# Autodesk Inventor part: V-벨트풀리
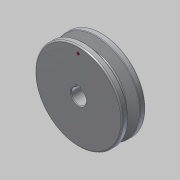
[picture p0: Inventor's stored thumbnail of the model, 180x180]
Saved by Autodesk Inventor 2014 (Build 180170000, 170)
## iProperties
Created: 2016-08
Part Number: V-벨트풀리
Material: 알루미늄 6061
Document SubType Name: Modeling
Designer: mduedu
Density: 2.71 g/cm^3
Appearance: 알루미늄 - 평지
Author: mduedu
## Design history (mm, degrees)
sketch "스케치1"
  geometry: L1 (0, 9.5)-(0, -9.5); L2 (0, 9.5)-(35, 9.5); L3 (35, 9.5)-(35, 4.825); L4 (35, 4.825)-(26, 2.074); L5 (26, 2.074)-(26, 0); L6 (0, 0)-(26, 0); L7 (0, -9.5)-(35, -9.5); L8 (35, -9.5)-(35, -4.825); L9 (35, -4.825)-(26, -2.074); L10 (26, -2.074)-(26, 0); L11 (32.3, 9.5)-(32.3, -9.5); 3 further points
  constraints: 22 end point, 6 point on line, 4 perpendicular, 3 symmetric about line, 1 coincident, 1 horizontal alignment, 1 midpoint, 1 parallel, 1 vertical
  dimensions: "d0" = 19 distance of L1.start L1.end; "d2" = 70 diameter of L8 L1; "d4" = 6.3 distance between parallel lines of L10 L11; "d5" = 2.7 distance between parallel lines of L11 L8; "d6" = 8 distance of point (32.3, -4) point (32.3, 4); "d7" = 34 deg angle of L9 L4
revolve "회전1" sketch "스케치1" stored, may be unused: angle "d8" = 90 deg
sketch "스케치2"
  geometry: L1 (-2, 0)-(2, 0); L2 (2, 0)-(2, 7.8); L3 (2, 7.8)-(-2, 7.8); L4 (-2, 7.8)-(-2, 0); C1 r 6 at (0, 0); 2 further points
  constraints: 8 end point, 2 coincident, 2 parallel, 1 centre point, 1 horizontal, 1 midpoint, 1 perpendicular
  dimensions: "d9" = 12 diameter of C1; "d11" = 4 distance of L2.end L3.end; "d12" = 7.8 distance of L1.end L2.end
extrude "돌출1" cut sketch "스케치2" stored distance "d13" = 10; taper "d14" = 0 deg
sketch "스케치4"
  geometry: C1 r 22 at (0, 0); C2 r 12 at (0, 0); 1 further point
  constraints: 2 centre point, 2 coincident
  dimensions: "d32" = 44 diameter of C1; "d34" = 24 diameter of C2
extrude "돌출2" cut sketch "스케치4" distance "d35" = 12; taper "d36" = 0 deg
fillet "모깎기1" dims "d20" = 0.5, "d21" = 1, "d37" = 1
fillet "모깎기6" dims "d38" = 3
chamfer "모따기1" distance "d26" = 0.5; stored, may be unused: second distance "d27" = 2, angle "d28" = 45 deg
sketch "스케치5" dims "d39" = 60
  geometry: C1 r 1 at (0, 30); 2 further points
  constraints: 2 vertical alignment, 1 centre point, 1 coincident, 2 other
  dimensions: "d40" = 2 diameter of C1
extrude "돌출3" join sketch "스케치5" distance "d41" = 0.5; taper "d42" = 0 deg
node "솔리드1"
